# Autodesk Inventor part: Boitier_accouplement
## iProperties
Shininess: 64.0
Length Units: 11269
Angle Units: 11279
Time Units: 11290
Mass Units: 11283
Length Display Precision: 3
Angle Display Precision: 2
Compacted: True
Part Number: Boitier_accouplement
Document SubType Name: Modeling
Created: 2008-02
Material: Acier inoxydable, austénitique
Designer: Pascal
Density: 0.0
Volumn: 0.0
Area: 0.0
PropertySet Name: Model Information
Control State: 0
Master: False
Checked Out: False
DESIGNATION: pièce
Author: Pascal
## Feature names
1. Révolution1 [Revolution]
2. Chanfrein1 [Chamfer]
3. Extrusion1
